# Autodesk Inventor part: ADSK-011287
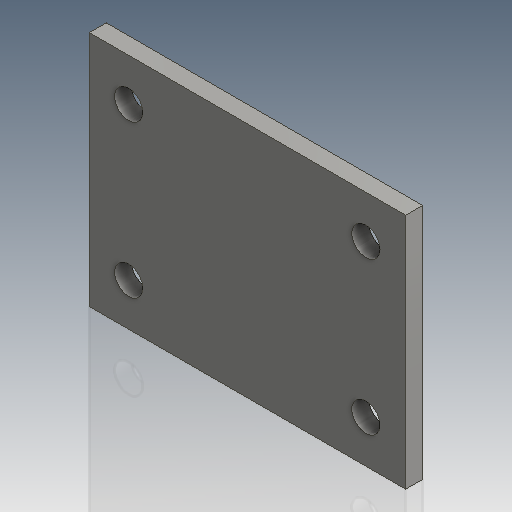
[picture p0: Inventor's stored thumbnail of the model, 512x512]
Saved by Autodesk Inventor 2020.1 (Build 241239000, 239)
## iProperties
Created: 1999-12
Part Number: ADSK-011287
Document SubType Name: Modeling
Designer: glanglot
Material: Pearson HRS
Density: 7.83 g/cm^3
Appearance: Steel
Mass: 1709.23 g
Surface Area: 536.634 cm^2
Volume: 218.293 cm^3
Control State: 0
Master: False
Checked Out: False
Shininess: 25.0
Length Units: 11272
Angle Units: 11279
Time Units: 11290
Mass Units: 11286
Length Display Precision: 3
Angle Display Precision: 2
Compacted: True
Cutlength: 5.25
Material Desc: FLAT,HRS,0.375X07.000
Material_Number: A084414
Dimensions: 5,3x0,4x7 in
Mass: 3,768 lb
DocNumber: ADSK-011287.ipt
Folder: 01 - Themengebiete\Simplification\01 - Packaging machine\
VDS_Category: 3D Komponenten
VLT_Material: Pearson HRS
Density: 7.83
Volumn: 218.2929933462445
Area: 536.6335967443599
PropertySet Name: Model Information
Author: glanglot
Revision Number: -
Title: base plate
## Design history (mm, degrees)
node "Extrusion1" dims "d10" = 9.525, "d11" = 0
  sketch "Sketch1"
    geometry: L1 (88.9, 66.675)-(-88.9, 66.675); L2 (-88.9, 66.675)-(-88.9, -66.675); L3 (-88.9, -66.675)-(88.9, -66.675); L4 (88.9, -66.675)-(88.9, 66.675); C1 r 7.938 at (-66.802, -42.799); C2 r 7.938 at (-66.802, 42.799); C3 r 7.938 at (66.547, 42.799); C4 r 7.938 at (66.547, -42.799); 3 further points
    constraints: 8 end point, 4 centre point, 3 horizontal alignment, 3 vertical alignment, 2 midpoint, 2 parallel, 1 horizontal, 1 perpendicular
    dimensions: "d0" = 177.8 distance of L1.start L1.end; "d1" = 133.35 distance of L3.end L1.start; "d2" = 15.875 diameter of C4; "d3" = 15.875 diameter of C3; "d4" = 15.875 diameter of C2; "d5" = 15.875 diameter of C1; "d6" = 22.35292 distance from line of L4 C4.centre; "d7" = 155.702 distance from line of C1.centre L4; "d8" = 23.876 distance from line of C2.centre L1; "d9" = 109.474 distance from line of C1.centre L1
workaxis "Arbeitsachse1"
node "Solide1"
node "Corps solides"
node "Corps surfaciques"
